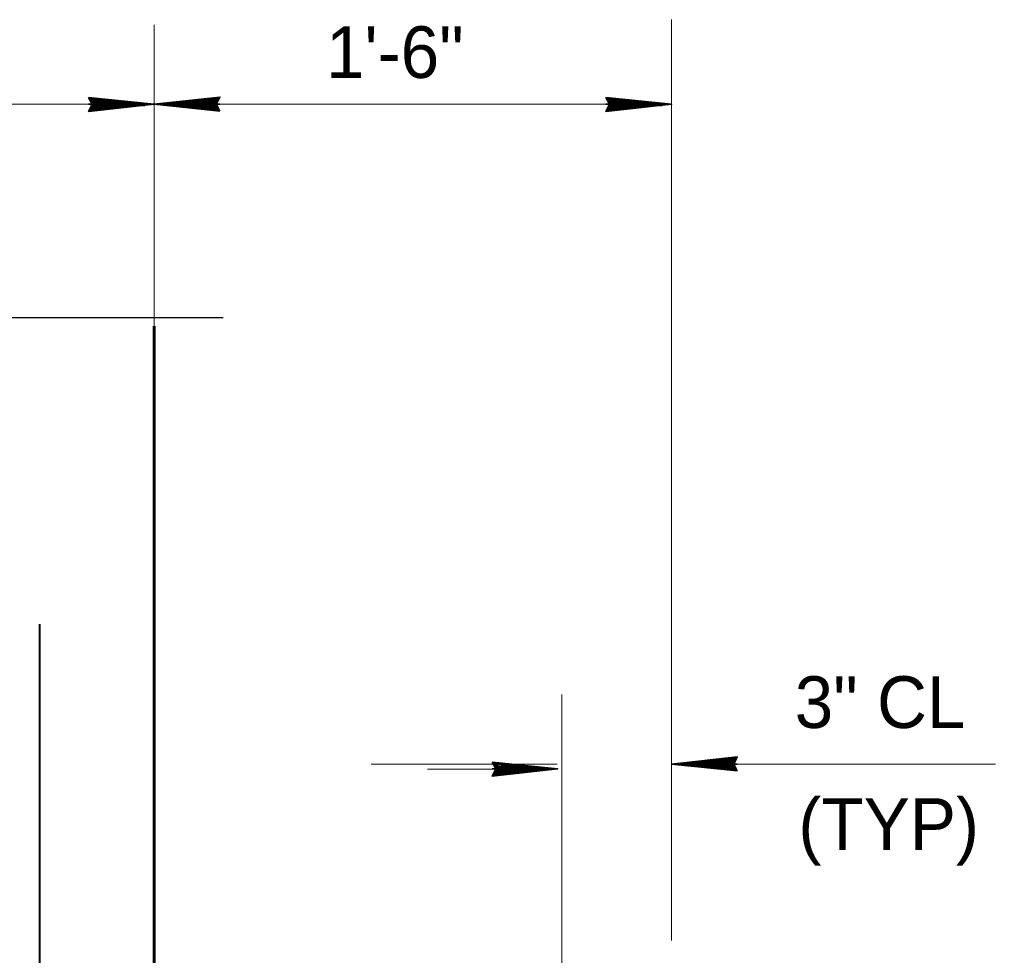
# Model space of a CAD drawing. Extents: x 14.14 to 17.34, y -1.61 to 0.38.
# Drawn here: x 15.7348 to 15.892, y 0.0709 to 0.2218 of the extents above; entities that cross this region are included whole.
import ezdxf

# ---------------------------------------------------------------- set-up
doc = ezdxf.new("R2010")
doc.units = 0
doc.header["$LTSCALE"] = 0.0033
doc.layers.add('1', color=7, linetype='Continuous', lineweight=40)

msp = doc.modelspace()

# ---------------------------------------------------------------- linework, layer by layer
at = {"layer": '1', "lineweight": 13}
for p, q in [((15.839833, 0.073333), (15.839833, 0.22175)), ((15.7565, 0.172333), (15.7565, 0.220917)), ((15.507083, 0.208083), (15.837333, 0.208083)), ((15.822167, 0.055083), (15.822167, 0.113)), ((15.791417, 0.10175), (15.821417, 0.10175)), ((15.8005, 0.100917), (15.821333, 0.100917)), ((15.841083, 0.10175), (15.892, 0.10175))]:
    msp.add_line(p, q, dxfattribs=at)
at = {"layer": '1', "lineweight": 35}
for p, q in [((15.746167, 0.209083), (15.754, 0.208167)), ((15.746167, 0.209083), (15.754, 0.208167)), ((15.766833, 0.209167), (15.7595, 0.208333)), ((15.8295, 0.209083), (15.837333, 0.208167)), ((15.8295, 0.209083), (15.837333, 0.208167)), ((15.745917, 0.208083), (15.7565, 0.208083)), ((15.746083, 0.207417), (15.753417, 0.208167)), ((15.746167, 0.209), (15.754, 0.208167)), ((15.746167, 0.208917), (15.754, 0.208083)), ((15.746167, 0.208917), (15.754, 0.207917)), ((15.746167, 0.20725), (15.7535, 0.208083)), ((15.746167, 0.207167), (15.7535, 0.207917)), ((15.746167, 0.207), (15.7535, 0.207833)), ((15.767083, 0.208083), (15.7565, 0.208083)), ((15.766833, 0.20725), (15.759, 0.20825)), ((15.766833, 0.20725), (15.759, 0.208083)), ((15.766833, 0.207083), (15.759, 0.208)), ((15.766833, 0.207083), (15.759, 0.208)), ((15.766833, 0.207167), (15.759, 0.208)), ((15.766833, 0.209), (15.7595, 0.20825)), ((15.766833, 0.208917), (15.7595, 0.208083)), ((15.766917, 0.20875), (15.759583, 0.208)), ((15.82925, 0.208083), (15.839833, 0.208083)), ((15.829417, 0.207417), (15.83675, 0.208167)), ((15.8295, 0.209), (15.837333, 0.208167)), ((15.8295, 0.208917), (15.837333, 0.208083)), ((15.8295, 0.208917), (15.837333, 0.207917)), ((15.8295, 0.20725), (15.836833, 0.208083)), ((15.8295, 0.207167), (15.836833, 0.207917)), ((15.8295, 0.207), (15.836833, 0.207833)), ((15.850167, 0.102833), (15.842833, 0.102)), ((15.850167, 0.102667), (15.842833, 0.101917)), ((15.850167, 0.102583), (15.842833, 0.10175)), ((15.85025, 0.102417), (15.842917, 0.101667)), ((15.810917, 0.101), (15.8215, 0.101)), ((15.811083, 0.100333), (15.818417, 0.101083)), ((15.811167, 0.102), (15.819, 0.101083)), ((15.811167, 0.102), (15.819, 0.101083)), ((15.811167, 0.101917), (15.819, 0.101083)), ((15.811167, 0.101833), (15.819, 0.101)), ((15.811167, 0.101833), (15.819, 0.100833)), ((15.811167, 0.100167), (15.8185, 0.101)), ((15.811167, 0.100083), (15.8185, 0.100833)), ((15.811167, 0.099917), (15.8185, 0.10075)), ((15.850417, 0.10175), (15.839833, 0.10175)), ((15.850167, 0.100917), (15.842333, 0.101917)), ((15.850167, 0.100917), (15.842333, 0.10175)), ((15.850167, 0.10075), (15.842333, 0.101667)), ((15.850167, 0.10075), (15.842333, 0.101667)), ((15.850167, 0.100833), (15.842333, 0.101667))]:
    msp.add_line(p, q, dxfattribs=at)
for points in [[(15.745917, 0.209167), (15.7565, 0.208083), (15.745917, 0.206917), (15.7465, 0.208083)], [(15.767083, 0.207), (15.7565, 0.208083), (15.767083, 0.20925), (15.7665, 0.208083)], [(15.82925, 0.209167), (15.839833, 0.208083), (15.82925, 0.206917), (15.829833, 0.208083)], [(15.746667, 0.208167), (15.751333, 0.20825), (15.751333, 0.208167), (15.750417, 0.208167), (15.746667, 0.20825), (15.749667, 0.208333), (15.7465, 0.208417), (15.74875, 0.2085), (15.7465, 0.208583), (15.75, 0.208333), (15.754667, 0.208167), (15.75375, 0.207917), (15.755, 0.207917), (15.746667, 0.207917), (15.749083, 0.20775), (15.7465, 0.20775), (15.751833, 0.208167), (15.7465, 0.2075)], [(15.766333, 0.208), (15.761667, 0.207917), (15.761667, 0.208), (15.762583, 0.208), (15.766333, 0.207917), (15.763333, 0.207833), (15.7665, 0.20775), (15.76425, 0.207667), (15.7665, 0.207583), (15.763, 0.207833), (15.758333, 0.208), (15.75925, 0.20825), (15.758, 0.20825), (15.766333, 0.20825), (15.763917, 0.208417), (15.7665, 0.208417), (15.761167, 0.208), (15.7665, 0.208667)], [(15.83, 0.208167), (15.834667, 0.20825), (15.834667, 0.208167), (15.83375, 0.208167), (15.83, 0.20825), (15.833, 0.208333), (15.829833, 0.208417), (15.832083, 0.2085), (15.829833, 0.208583), (15.833333, 0.208333), (15.838, 0.208167), (15.837083, 0.207917), (15.838333, 0.207917), (15.83, 0.207917), (15.832417, 0.20775), (15.829833, 0.20775), (15.835167, 0.208167), (15.829833, 0.2075)], [(15.850417, 0.100667), (15.839833, 0.10175), (15.850417, 0.102917), (15.849833, 0.10175)], [(15.849667, 0.101667), (15.845, 0.101583), (15.845, 0.101667), (15.845917, 0.101667), (15.849667, 0.101583), (15.846667, 0.1015), (15.849833, 0.101417), (15.847583, 0.101333), (15.849833, 0.10125), (15.846333, 0.1015), (15.841667, 0.101667), (15.842583, 0.101917), (15.841333, 0.101917), (15.849667, 0.101917), (15.84725, 0.102083), (15.849833, 0.102083), (15.8445, 0.101667), (15.849833, 0.102333)], [(15.810917, 0.102083), (15.8215, 0.101), (15.810917, 0.099833), (15.8115, 0.101)], [(15.811667, 0.101083), (15.816333, 0.101167), (15.816333, 0.101083), (15.815417, 0.101083), (15.811667, 0.101167), (15.814667, 0.10125), (15.8115, 0.101333), (15.81375, 0.101417), (15.8115, 0.1015), (15.815, 0.10125), (15.819667, 0.101083), (15.81875, 0.100833), (15.82, 0.100833), (15.811667, 0.100833), (15.814083, 0.100667), (15.8115, 0.100667), (15.816833, 0.101083), (15.8115, 0.100417)]]:
    msp.add_lwpolyline(points, close=True, dxfattribs=at)
for points in [[(15.766333, 0.208), (15.76675, 0.20725), (15.7665, 0.2075), (15.766333, 0.207833), (15.766083, 0.20775), (15.76625, 0.207417), (15.766417, 0.208167), (15.766583, 0.208667), (15.766833, 0.209083)], [(15.746667, 0.208167), (15.74625, 0.208917), (15.7465, 0.208667), (15.746667, 0.208333), (15.746917, 0.208417), (15.74675, 0.20875), (15.746583, 0.208), (15.746417, 0.2075), (15.746167, 0.207083)], [(15.83, 0.208167), (15.829583, 0.208917), (15.829833, 0.208667), (15.83, 0.208333), (15.83025, 0.208417), (15.830083, 0.20875), (15.829917, 0.208), (15.82975, 0.2075), (15.8295, 0.207083)], [(15.849667, 0.101667), (15.850083, 0.100917), (15.849833, 0.101167), (15.849667, 0.1015), (15.849417, 0.101417), (15.849583, 0.101083), (15.84975, 0.101833), (15.849917, 0.102333), (15.850167, 0.10275)], [(15.811667, 0.101083), (15.81125, 0.101833), (15.8115, 0.101583), (15.811667, 0.10125), (15.811917, 0.101333), (15.81175, 0.101667), (15.811583, 0.100917), (15.811417, 0.100417), (15.811167, 0.1)]]:
    msp.add_lwpolyline(points, dxfattribs=at)
at = {"layer": '1', "lineweight": 25}
msp.add_lwpolyline([(15.577333, 0.173833), (15.660667, 0.173833), (15.666583, 0.167917), (15.678333, 0.179667), (15.68425, 0.17375), (15.767583, 0.17375)], dxfattribs=at)
at = {"layer": '1', "lineweight": 60}
msp.add_lwpolyline([(15.7565, 0.172333), (15.7565, 0.068167), (15.839833, 0.068167)], dxfattribs=at)
at = {"layer": '1'}
msp.add_lwpolyline([(15.738, 0.124333), (15.738, 0.011333), (15.8005, 0.011333)], dxfattribs=at)

# ---------------------------------------------------------------- texts
for s, height, p in [('1\'-6"', 0.008333, (15.784167, 0.212333)), ('3" CL', 0.008334, (15.859667, 0.107583)), ('(TYP)', 0.008334, (15.86025, 0.087917))]:
    msp.add_text(s, height=height, dxfattribs=at).set_placement(p)

doc.saveas('drawing.dxf')
